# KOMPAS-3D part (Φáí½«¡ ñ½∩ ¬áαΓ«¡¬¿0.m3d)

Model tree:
1. Эскиз:1
2. Операция выдавливания:1
     Толщина стенки 2 = 6; Расстояние 1 = 0.6
3. Эскиз:2
4. Операция выдавливания:2
     Толщина стенки 1 = 12; Толщина стенки 2 = 12; Расстояние 1 = 0.6; Расстояние 2 = 0.6
5. Эскиз:3
6. Операция выдавливания:3
     Толщина стенки 1 = 12; Толщина стенки 2 = 12; Расстояние 1 = 0.6; Расстояние 2 = 0.6
7. Эскиз:4
8. Операция выдавливания:4
     Толщина стенки 1 = 35; Толщина стенки 2 = 35; Расстояние 1 = 0.6; Расстояние 2 = 0.6
9. Эскиз:5
10. Вырезать элемент выдавливания:1
     Расстояние 1 = 10
11. Эскиз:6
12. Вырезать элемент выдавливания:2
     Расстояние 1 = 10
13. Эскиз:7
14. Вырезать элемент выдавливания:3
     Расстояние 1 = 10
